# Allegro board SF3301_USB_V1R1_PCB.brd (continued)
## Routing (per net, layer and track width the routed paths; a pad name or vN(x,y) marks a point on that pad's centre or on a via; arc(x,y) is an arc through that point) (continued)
6314_ISEN: length 46.5
  TOP w0.254: v1(82.26,75.71) 82.77,76.22 R190.1
  TOP w0.508: v1(85.18,65.42) 85.18,65.17 84.93,64.91 84.12,64.91 83.78,65.24 83.78,68.57 85.82,70.6 85.82,78.91 78.98,85.74 75.28,85.74 v1(75.15,85.87)
  BOTTOM w0.254: R202.1 v1(75.15,85.87) ; Q21.5 80.84,73.73 80.48,74.08 80.48,76.34 79.52,77.31 78.02,77.31 77.18,78.15 C361.2 77.05,78.37 75.02,78.37 74.74,78.66 U13.24
  BOTTOM w0.508: L6.2 v1(85.18,65.42)
  vias: v1(79.72,75.71) v1(79.72,74.44) v1(79.72,73.17) v1(79.72,71.9) v1(80.99,75.71) v1(80.99,74.44) v1(80.99,73.17) v1(80.99,71.9) v1(82.26,74.44) v1(82.26,73.17) v1(82.26,71.9) v1(83.53,75.71) v1(83.53,74.44) v1(83.53,73.17) v1(83.53,71.9)
6314_ISEN-: length 5.6
  BOTTOM w0.254: C364.2 R204.2 73.42,86.96 R202.2 C362.1 73.42,84.36 72.97,83.91 U13.15
ADJ_TP: length 27.9
  TOP w0.508: R59.1 17.26,64.76 R60.1
  TOP w0.635: v1(13.81,51.96) 15.19,53.34 15.19,62.36 17.24,64.4 R59.1
  BOTTOM w0.381: 9.87,46.42 9.64,46.19 9.64,45.28 10.41,44.51 11.01,44.51 C276.2 11.39,44.51 11.93,44.51 R76.2
  BOTTOM w0.635: v1(13.81,51.96) 9.87,48.02 9.87,46.42
BTC_GNDS_0: length 34.9
  TOP w0.381: U5.A20 38.64,73.1 38,73.1
  TOP w0.508: 38,73.1 37.88,73.1 v2(37.43,73.55) 37.18,73.8 37.18,85.61 38.93,87.36 J6.1
  TOP w0.762: J6.5 J6.3 J6.1
  BOTTOM w0.381: v2(37.43,73.55) 37.88,73.1 38.07,73.1 C38.1
BTC_GNDS_1: length 73.2
  TOP w0.381: U5.P1 49.42,57.48 49.42,56.95 v2(49.41,56.94) 49.79,56.56 55.06,56.56 55.59,56.02
  TOP w0.762: v1(59.73,87.65) 59.73,89.22 58.89,90.06 58.89,98.57 58.13,99.33 56.99,99.33 55.08,101.23 51.37,101.23 J8.1 J8.3 J8.5 ; v1(60.21,75.73) 60.21,74.23 61.94,72.51 61.94,57.67 60.29,56.02 55.59,56.02
  BOTTOM w0.381: C39.1 49.88,56.47 v2(49.41,56.94)
  BOTTOM w0.635: v1(59.73,87.65) 60.11,87.26 60.11,76.9 60.2,76.82 60.2,75.8 60.18,75.77 v1(60.21,75.73)
BTC_PGD: length 105.2
  TOP w0.254: v1(59.43,76.49) 59.55,76.62 61.51,76.62 62.7,75.43 62.7,74.39 64.46,72.63 64.46,58.94 65.12,58.28 65.12,53.36 62.45,50.69 37.94,50.69 34,46.75 34,34.94 31.08,32.02 25.24,32.02 v1(23.97,30.75)
  BOTTOM w0.254: R127.2 22.85,29.37 23.97,30.5 v1(23.97,30.75) ; R152.2 61.43,91.96 60.8,91.96 R233.2 R181.2 60.16,89.58 58.99,88.41 58.99,83.2 59.32,82.87 59.32,76.6 v1(59.43,76.49)
BTC_VDD: length 322
  TOP w0.381: v2(46.64,56.3) U5.M1 v2(48.24,57.9) U5.N2 U5.P3 v2(49.84,59.5) U5.R4 ; U5.K13 v2(45.84,67.5) U5.J14 U5.H15 v2(44.24,69.1) U5.G16 U5.E18 v2(41.84,71.5) U5.D19 U5.C20 v2(40.24,73.1) ; v2(38.64,62.7) U5.A8 U5.B9 v2(40.24,64.3) U5.C10 U5.D11 v2(41.84,65.9) U5.E12 ; U5.P9 v2(49.04,63.5) U5.N8 U5.M7 v2(47.44,61.9) v2(46.64,61.1) U5.K5 U5.J4 v2(45.04,59.5) U5.H3 U5.G2 v2(43.44,57.9) U5.F1 v2(41.84,56.3) ; U5.U2 v2(51.44,57.9) U5.T1 ; U5.J20 v2(45.84,73.1) U5.K21 ; U5.J20 U5.K19 v2(46.64,72.3) U5.L20 ; U5.J20 v2(45.04,73.1) U5.H21 ; v2(40.24,56.3) U5.D1 v2(41.84,57.9) U5.E2 U5.F3 v2(43.44,59.5) U5.G4 U5.H5 v2(45.04,61.1) v2(45.84,61.9) U5.K7 U5.L8 v2(47.44,63.5) U5.M9 U5.N10 v2(49.04,65.1) U5.P11 ; U5.N12 v2(48.24,65.9) U5.M11 v2(47.44,65.1) U5.L10 U5.K9 v2(45.84,63.5) U5.J8 U5.H7 v2(44.24,61.9) v2(43.44,61.1) U5.F5 U5.E4 v2(41.84,59.5) U5.D3 U5.C2 v2(40.24,57.9) U5.B1 ; v2(38.64,57.9) U5.A2 U5.B3 v2(40.24,59.5) U5.C4 U5.D5 v2(41.84,61.1) U5.E6 U5.G8 v2(44.24,63.5) U5.H9 U5.J10 v2(45.84,65.1) U5.K11 v2(46.64,65.9) U5.L12 ; U5.U4 v2(51.44,59.5) U5.T3 U5.R2 v2(49.84,57.9) ; v2(38.64,71.5) U5.A18 U5.B17 v2(40.24,69.9) U5.C16 U5.D15 v2(41.84,68.3) U5.E14 ; U5.N22 v2(48.24,73.9) U5.M21 ; U5.D21 v2(41.84,73.1) U5.E20 U5.F19 v2(43.44,72.3) U5.G20 U5.H19 v2(45.04,71.5) v2(45.84,70.7) U5.K17 U5.L16 v2(47.44,69.1) U5.M15 U5.N14 v2(49.04,67.5) U5.P13 ; U5.D13 v2(41.04,67.5) U5.C14 v2(40.24,68.3) U5.B15 U5.A16 v2(38.64,69.9) ; U5.J12 v2(45.04,65.9) U5.H11 v2(44.24,65.1) U5.G10 U5.E8 v2(41.84,62.7) U5.D7 U5.C6 v2(40.24,61.1) U5.B5 U5.A4 v2(38.64,59.5) ; U5.P15 v2(49.04,69.1) U5.N16 U5.M17 v2(47.44,70.7) ; U5.N17 v2(49.04,70.7) U5.P17 ; v2(38.64,64.3) U5.A10 U5.B11 v2(40.24,65.9) U5.C12 ; U5.H13 v2(44.24,67.5) U5.G14 U5.E16 v2(41.84,69.9) U5.D17 U5.C18 v2(40.24,71.5) U5.B19 ; v2(38.64,65.9) U5.A12 U5.B13 v2(39.44,67.5) U5.A14 v2(38.64,68.3) ; v2(38.64,61.1) U5.A6 U5.B7 v2(40.24,62.7) U5.C8 U5.D9 v2(41.84,64.3) U5.E10 v2(43.44,65.9) U5.G12 ; v2(45.04,56.3) U5.K1 v2(46.64,57.9) U5.L2 U5.M3 v2(48.24,59.5) U5.N4 U5.P5 v2(49.84,61.1) ; v2(44.24,70.7) U5.H17 U5.J16 v2(45.84,69.1) U5.K15 U5.L14 v2(47.44,67.5) U5.M13 ; U5.P7 v2(49.04,61.9) v2(48.24,61.1) U5.M5 U5.L4 v2(46.64,59.5) U5.K3 U5.J2 v2(45.04,57.9) U5.H1 v2(43.44,56.3)
  TOP w0.508: v1(14.92,46.99) 18.12,50.19 18.12,52.06 ; v1(14.01,46.11) 13.93,46.19 13.93,48.4 16.22,50.69 16.22,52.09
  ART02 w0.508: v1(21.68,47.51) 21.68,46.12 24.57,43.23 32.64,43.23 36.35,39.52 37.69,39.52 v1(38.7,40.53) ; v1(27.14,44.47) 27.14,44.59 27.9,45.35 33.57,45.35 36.64,48.43 60.01,48.43 61.31,47.13 61.31,43.7 62.3,42.71 64.33,42.71 64.73,43.12 v1(64.73,43.96) ; v1(16.6,56.66) 16.6,56.02 23.6,49.03 v1(23.6,46.57) ; v1(25.98,46.5) 25.98,52.03 25.42,52.59 25.42,81.98 27.4,83.96 27.4,94.88 24.6,97.68 v1(24.6,98.06)
  BOTTOM w0.305: R95.1 v1(14.01,46.11) ; R92.1 v1(14.92,46.99)
  BOTTOM w0.381: D6.A 20.76,52.95 21.51,52.95 ; R89.1 16.8,47.96 17.31,47.96 21.51,52.17
  BOTTOM w0.508: 30.39,48.33 30.32,48.25 R70.1 ; v1(21.68,47.51) 21.68,47.44 C280.1 ; v1(23.6,46.57) 23.6,45.77 C282.1 ; C284.1 27.14,43.92 v1(27.14,44.47) ; v1(25.98,46.5) 25.98,44.55 C283.1
  vias: v1(16.6,59.2) v1(16.6,57.93) v1(17.62,59.2) v1(17.62,57.93) v1(17.62,56.66) v1(20.79,59.2) v1(20.79,57.93) v1(20.79,56.66) v1(22.06,59.2) v1(22.06,57.93) v1(22.06,56.66) v1(23.33,109.36) v1(23.33,108.09) v1(23.33,106.82) v1(23.33,105.55) v1(23.33,104.28) v1(23.33,103.01) v1(23.33,101.74) v1(23.33,100.47) v1(23.33,99.2) v1(23.33,65.42) v1(23.33,64.15) v1(23.33,62.88) v1(23.33,61.61) v1(23.33,60.34) v1(23.33,59.2) v1(23.33,57.93) v1(23.33,56.66) v1(23.33,54.75) v1(23.33,52.97) v1(24.6,109.36) v1(24.6,108.09) v1(24.6,106.82) v1(24.6,105.55) v1(24.6,104.28) v1(24.6,103.01) v1(24.6,101.74) v1(24.6,100.47) v1(24.6,99.2) v1(25.87,97.93) v1(26.51,67.07) v1(26.51,65.8) v1(26.51,64.53) v1(26.51,62.37) v1(26.51,60.47) v1(26.51,57.93) v1(26.51,56.02) v1(27.14,97.93) v1(27.14,76.98) v1(27.14,74.44) v1(27.14,68.09) v1(27.14,63.64) v1(27.78,96.66) v1(27.78,81.42) v1(27.78,80.15) v1(27.78,78.88) v1(28.41,109.36) v1(28.41,108.09) v1(28.41,100.47) v1(28.41,99.2) v1(28.41,97.93) v1(28.41,68.09) v1(28.41,63.64) v1(28.41,62.37) v1(28.41,60.47) v1(28.41,57.93) v1(28.41,56.02) v1(28.67,76.98) v1(28.67,74.44) v1(29.05,96.66) v1(29.05,94.12) v1(29.05,91.58) v1(29.05,89.68) v1(29.05,87.77) v1(29.05,83.96) v1(29.05,82.69) v1(29.05,81.42) v1(29.05,80.15) v1(29.05,78.88) v1(29.05,67.07) v1(29.05,65.8) v1(29.05,64.53) v1(29.68,109.36) v1(29.68,108.09) v1(29.68,100.47) v1(29.68,99.2) v1(29.68,97.93) v1(30.32,96.66) v1(30.32,94.12) v1(30.32,91.58) v1(30.32,89.68) v1(30.32,87.77) v1(30.32,83.96) v1(30.32,82.69) v1(30.32,81.42) v1(30.32,80.15) v1(30.32,76.98) v1(30.32,74.44) v1(30.32,67.07) v1(30.32,65.8) v1(30.32,64.53) v1(30.95,109.36) v1(30.95,108.09) v1(30.95,106.82) v1(30.95,105.55) v1(30.95,104.28) v1(30.95,103.01) v1(30.95,101.74) v1(30.95,100.47) v1(30.95,99.2) v1(30.95,97.93) v1(31.59,96.66) v1(31.59,94.12) v1(31.59,91.58) v1(31.59,89.68) v1(31.59,87.77) v1(31.59,83.96) v1(31.59,82.69) v1(31.59,81.42) v1(31.59,67.07) v1(31.59,65.8) v1(31.59,64.53) v1(31.59,63.26) v1(31.59,61.74) v1(31.59,60.47) v1(32.86,96.66) v1(32.86,94.12) v1(32.86,91.58) v1(32.86,89.68) v1(32.86,87.77) v1(32.86,85.23) v1(32.86,83.96) v1(32.86,80.91) v1(32.86,78.12) v1(32.86,76.98) v1(32.86,74.44) v1(32.86,67.07) v1(32.86,65.8) v1(32.86,64.53) v1(32.86,63.26) v1(32.86,61.74) v1(32.86,60.47) v1(33.49,70.12) v1(33.49,68.09) v1(34.13,94.12) v1(34.13,91.58) v1(34.13,89.68) v1(34.13,87.77) v1(34.13,85.23) v1(34.13,83.96) v1(34.13,80.91) v1(34.13,78.12) v1(34.13,76.98) v1(34.13,74.44) v1(34.13,71.9) v1(34.13,63.26) v1(34.13,61.74) v1(34.13,60.47) v1(34.76,69.99) v1(34.76,68.09) v1(35.27,59.2) v1(35.27,56.66) v1(35.27,55.39) v1(35.27,54.12) v1(35.4,94.12) v1(35.4,91.58) v1(35.4,89.68) v1(35.4,87.77) v1(35.4,85.23) v1(35.4,83.96) v1(35.4,80.91) v1(35.4,78.12) v1(35.4,76.98) v1(35.4,74.44) v1(35.4,73.17) v1(35.4,71.9) v1(36.03,69.99) v1(36.03,68.09) v1(36.03,67.07) v1(36.03,65.8) v1(36.03,64.53) v1(36.03,63.26) v1(36.03,61.74) v1(36.03,60.47) v1(36.41,75.71) v1(36.41,74.44) v1(36.41,73.17) v1(36.67,71.9) v1(36.67,59.2) v1(36.67,56.66) v1(37.43,55.39) v1(37.43,54.12) v1(37.94,45.23) v1(37.94,43.96) v1(38.57,46.24) v1(39.21,45.23) v1(39.21,43.96) v1(39.84,55.39) v1(39.84,54.12) v1(39.84,46.37) v1(40.48,45.23) v1(40.48,43.96) v1(41.11,46.5) v1(41.49,53.61) v1(42.38,46.5) v1(43.02,53.61) v1(43.65,46.5) v1(44.54,55.39) v1(44.54,54.12) v1(44.92,46.5) v1(46.19,46.5) v1(46.83,55.39) v1(46.83,54.12) v1(47.46,46.5) v1(47.46,45.23) v1(47.46,43.96) v1(48.1,55.39) v1(48.73,46.5) v1(48.73,45.23) v1(48.73,43.96) v1(48.99,54.12) v1(50,46.5) v1(50,45.23) v1(50,43.96) v1(50.64,54.12) v1(50.76,55.77) v1(51.27,46.5) v1(51.27,45.23) v1(51.78,53.74) v1(51.91,55.77) v1(52.54,46.5) v1(52.54,45.23) v1(52.54,43.96) v1(53.3,55.77) v1(53.43,53.74) v1(53.81,46.5) v1(53.81,45.23) v1(54.57,54.24) v1(54.57,43.96) v1(54.7,55.77) v1(55.08,46.5) v1(55.08,45.23) v1(56.35,46.5) v1(56.35,45.23) v1(56.61,43.96) v1(57.62,46.5) v1(57.62,45.23) v1(58.64,43.96) v1(58.89,45.23) v1(62.45,46.37) v1(62.45,45.23) v1(62.45,43.96) v1(63.59,46.37) v1(63.59,45.23) v1(63.59,43.96) v1(64.61,48.78) v1(64.61,47.64) v1(64.61,46.37) v1(64.73,45.23) v1(66.13,46.37) v1(67.91,48.78) v1(67.91,47.64) v1(67.91,46.37) v1(68.93,47.64) v1(68.93,46.5) v1(69.94,47.64) v1(69.94,46.37) v1(70.83,46.5) v1(70.83,45.1) v1(70.83,43.83) v1(71.97,46.5) v1(72.1,45.1) v1(72.1,43.83) v1(73.37,45.1) v1(73.37,43.83)
BTC_VDDS_0: length 43.2
  TOP w0.381: v2(38.52,73.9) 38.64,73.9 U5.A21
  TOP w0.508: v2(38.52,73.9) 38.35,73.9 37.94,74.31 37.94,84.98 39.84,86.88 39.84,96.79 40.6,97.55 40.6,106.8 38.93,108.47
  TOP w0.762: 38.93,108.47 33.85,108.47
  BOTTOM w0.381: v2(38.52,73.9) 38.17,74.25 C38.2
BTC_VDDS_1: length 80.5
  TOP w0.381: U5.P2 v2(49.04,57.9) ; 55.97,55.01 49.75,55.01 v2(49.11,55.64)
  TOP w0.762: v1(60.75,87.95) 60.75,89.7 59.91,90.54 59.91,99.3 50.74,108.47 44.64,108.47 ; v1(61.2,75.76) 61.2,74.67 62.96,72.91 62.96,57.17 60.8,55.01 55.97,55.01
  BOTTOM w0.381: v2(49.11,55.64) 48.86,55.9 C39.2 48.83,56.3 48.83,57.69 v2(49.04,57.9)
  BOTTOM w0.635: v1(61.2,75.76) 61.2,77.03 60.98,77.26 60.98,87.72 v1(60.75,87.95)
DNRX0: length 48.1
  TOP w0.254: v1(71.72,53.74) 72.86,54.88 72.86,56.53 67.83,61.56 67.83,73.67 62.62,78.88 51.53,78.88 v1(51.02,78.37)
  TOP w0.381: U5.R22 v2(50.64,74.7)
  BOTTOM w0.254: v1(51.02,78.37) 51.12,78.27 51.12,76.95 50.46,76.29 50.46,74.89 v2(50.64,74.7) ; 70.83,53.61 70.96,53.74 v1(71.72,53.74) 72.38,53.74 R33.1
DNRX1: length 40.2
  TOP w0.254: v1(71.72,55.64) 66.82,60.54 66.82,73.24 62.19,77.87 54.32,77.87 53.56,77.1 52.42,77.1 52.03,76.72 52.03,75.29 U5.U23
  BOTTOM w0.254: 70.83,55.64 v1(71.72,55.64) 72.51,55.64 R41.1
DNTX0: length 44.3
  TOP w0.254: v1(71.72,54.63) 72.35,55.26 72.35,56 67.33,61.03 67.33,73.5 62.45,78.37 52.03,78.37 51.4,77.74 51.4,76.47 50.24,75.31 U5.R23
  BOTTOM w0.254: 70.83,54.63 v1(71.72,54.63) 72.51,54.63 R35.1
DNTX1: length 47.3
  TOP w0.254: v1(51.02,79.39) 63.85,79.39 65.37,77.87 65.37,76.88 68.34,73.9 68.34,62.07 v1(72.99,57.42)
  TOP w0.381: U5.U22 v2(51.44,74.7)
  BOTTOM w0.254: v1(72.99,57.42) 72.53,56.96 R37.1 72.51,56.66 70.83,56.66 ; v1(51.02,79.39) 51.63,78.78 51.63,76.7 50.97,76.04 50.97,75.18 v2(51.44,74.7)
FB_VSS: length 32.1
  BOTTOM w0.203: 16.1,35.44 U11.3
  BOTTOM w0.254: 16.1,35.44 15.97,35.31 15.97,34.69
  BOTTOM w0.381: 19.51,30.1 18.24,31.37 18.14,31.37 15.97,33.54 15.97,34.69
  BOTTOM w0.508: R122.2 29.3,42.97 C271.1
  BOTTOM w0.635: 19.51,30.1 21.29,28.31 26.02,28.31 29.48,31.77 29.48,42.13 29.33,42.28 C271.1
ISL6314_VID0: length 3.1
  BOTTOM w0.254: R199.2 70.47,77.25 U13.31
ISL6314_VID1: length 2.8
  BOTTOM w0.254: R198.2 69.94,75.96 70.97,76.99 U13.30
ISL6314_VID2: length 2.5
  BOTTOM w0.254: R197.2 71.08,76.22 71.47,76.6 U13.29
ISL6314_VID3: length 2.5
  BOTTOM w0.254: R196.2 72.23,76.6 71.97,76.85 U13.28
ISL6314_VID4: length 2.7
  BOTTOM w0.254: R195.2 73.37,76.22 72.47,77.12 U13.27
ISL6314_VID5: length 3
  BOTTOM w0.254: R194.2 74.51,75.83 72.97,77.38 U13.26
ISL6314_VID6: length 3.3
  BOTTOM w0.254: U13.25 73.47,77.77 R193.2
ISL6314_VID7: length 3.6
  BOTTOM w0.254: R191.2 68.42,76.34 68.8,76.34 69.97,77.51 U13.32
ISN1: length 6.9
  BOTTOM w0.229: U11.18 15.89,42.81 15.89,43.71
  BOTTOM w0.254: R85.2 13.35,46.79 13.35,45.88 14.57,44.66 14.91,44.66 R95.2 15.89,44.23 15.89,43.71
ISN24: length 7.2
  BOTTOM w0.229: U11.19 16.59,42.83 16.59,44.41
  BOTTOM w0.254: R87.2 14.29,46.72 15.47,45.54 15.83,45.54 16.09,45.8 R92.2 16.59,45.31 16.59,44.41
ISN35: length 7.5
  BOTTOM w0.229: U11.20 17.25,42.89 17.25,44.92
  BOTTOM w0.254: R79.2 15.18,47.7 16.4,46.48 16.75,46.48 R89.2 17.25,46.52 17.25,44.92
ISP1: length 7
  BOTTOM w0.203: 22.21,42.36 20.77,42.36 20.35,41.93 20.35,41.86 19.82,41.34 U11.25
  BOTTOM w0.381: 22.21,42.36 23.4,41.17 24.39,41.17 C284.2
  BOTTOM w0.508: R96.2 24.55,41.33 C284.2
ISP2: length 5.2
  BOTTOM w0.203: 22.05,42.94 20.7,42.94 19.89,42.12 19.89,42.11 U11.24
  BOTTOM w0.254: 22.05,42.94 22.24,43.13 R93.2
  BOTTOM w0.381: C283.2 R93.2
ISP3: length 4.8
  BOTTOM w0.203: 19.91,42.85 19.61,42.55 U11.23
  BOTTOM w0.254: 20.67,43.6 19.91,42.85
  BOTTOM w0.381: R90.2 C282.2 21.44,43.6 20.67,43.6
ISP4: length 5.2
  BOTTOM w0.203: U11.22 19.78,43.43 19.78,43.65
  BOTTOM w0.381: C280.2 19.78,45.54 19.78,43.65
  BOTTOM w0.508: R86.2 C280.2
ISP5: length 5.7
  BOTTOM w0.203: U11.21 18.89,43.26 18.89,43.66
  BOTTOM w0.381: 18.89,43.66 18.89,45.55 18.13,46.31 18.13,47.48 R103.2
LTC_PGD: length 79.8
  TOP w0.254: v1(25.62,31.38) 31.21,31.38 34.51,34.69 34.51,46.5 38.19,50.18 62.96,50.18 65.62,52.85 65.62,58.54 65.12,59.05 v1(65.12,72.02)
  BOTTOM w0.254: v1(25.62,31.38) 24.86,32.15 R110.2 ; R173.1 65.8,73.85 65.8,72.71 v1(65.12,72.02)
LTC_PGD_R: length 6.2
  BOTTOM w0.203: C359.1 67.76,76.9 68.6,76.9 69.27,77.58 U13.1 ; C359.1 67.58,76.77 67.15,77.21 67.11,77.21 66.55,77.76 R143.2 ; C359.1 67.58,76.65 R173.2
LTC_VDD: length 116.6
  TOP w0.381: U5.AB1 v2(56.24,57.9) U5.AC2 v2(57.04,57.9) ; U5.T7 v2(50.64,62.7) U5.R8 ; v2(57.04,61.1) U5.AC6 v2(56.24,61.1) U5.AB5 U5.AA4 v2(54.64,59.5) U5.Y3 U5.W2 v2(53.04,57.9) U5.V1 ; U5.T19 v2(51.44,71.5) ; U5.W16 v2(53.84,69.9) U5.Y17 U5.AA18 v2(55.44,71.5) U5.AB19 U5.AC20 v2(57.04,73.1) ; v2(53.04,62.7) U5.W8 U5.Y9 v2(54.64,64.3) U5.AA10 U5.AB11 v2(56.24,65.9) U5.AC12 v2(57.04,65.9) ; v2(57.04,59.5) U5.AC4 v2(56.24,59.5) U5.AB3 U5.AA2 v2(54.64,57.9) U5.Y1 ; v2(57.04,64.3) U5.AC10 v2(56.24,64.3) U5.AB9 U5.AA8 v2(54.64,62.7) U5.Y7 U5.W6 v2(53.04,61.1) U5.V5 ; U5.R12 v2(50.64,65.9) U5.T11 U5.U10 v2(52.24,64.3) ; U5.V3 v2(53.04,59.5) U5.W4 U5.Y5 v2(54.64,61.1) U5.AA6 U5.AB7 v2(56.24,62.7) U5.AC8 v2(57.04,62.7) ; v2(52.24,68.3) U5.U14 U5.T15 51.04,68.7 v2(50.64,69.1) U5.R16 ; U5.Y21 v2(53.84,73.1) U5.W20 v2(53.04,73.1) U5.V21 ; v2(52.24,65.9) U5.U12 U5.T13 51.04,67.1 v2(50.64,67.5) U5.R14 ; v2(52.24,69.9) U5.U16 U5.T17 v2(50.64,70.7) ; U5.AB21 v2(55.44,73.1) U5.AA20 U5.Y19 v2(53.84,71.5) U5.W18 v2(53.04,71.5) U5.V19 U5.U20 v2(51.44,73.1) U5.T21 ; v2(51.44,61.1) U5.T5 ; U5.W14 v2(53.84,68.3) U5.Y15 U5.AA16 v2(55.44,69.9) U5.AB17 U5.AC18 v2(57.04,71.5) ; v2(57.04,68.3) U5.AC14 v2(56.24,67.5) U5.AB13 U5.AA12 v2(54.64,65.9) U5.Y11 U5.W10 v2(53.04,64.3) ; U5.R10 v2(50.64,64.3) U5.T9 U5.U8 v2(52.24,62.7) ; v2(53.04,65.9) U5.W12 U5.Y13 v2(54.64,67.5) U5.AA14 v2(55.44,68.3) U5.AB15 U5.AC16 v2(57.04,69.9) ; v2(53.04,73.9) U5.W22
  TOP w0.508: v1(85.18,64.02) 85.03,64.18 83.81,64.18 83.05,64.94 83.05,68.88 83.48,69.31 85.08,70.91 85.08,78.6 78.68,85 75.3,85 v1(75.15,84.85)
  BOTTOM w0.254: v1(75.15,84.85) C362.2 74.44,84.65 73.47,83.68 U13.16
  BOTTOM w0.305: R206.1 R208.2 ; R208.2 61.31,71.26 ; R208.2 60.62,72.15 60.59,72.13
  BOTTOM w0.508: L6.1 v1(85.18,64.02)
  vias: v1(58.26,69.99) v1(58.26,68.09) v1(58.38,72.66) v1(58.89,66.18) v1(58.89,64.28) v1(58.89,63.01) v1(58.89,61.74) v1(58.89,60.47) v1(58.89,59.2) v1(58.89,57.93) v1(59.53,72.66) v1(59.53,69.99) v1(59.53,68.09) v1(60.16,66.18) v1(60.16,64.28) v1(60.16,63.01) v1(60.16,61.74) v1(60.16,60.47) v1(60.16,59.2) v1(60.16,57.93) v1(60.54,72.66) v1(60.8,69.99) v1(60.8,68.09) v1(70.36,60.88) v1(71.97,59.32) v1(77.82,57.55) v1(79.72,59.96) v1(79.72,57.55) v1(79.85,64.28) v1(79.85,62.88) v1(79.85,61.48) v1(81.5,61.36) v1(81.5,59.96) v1(82.26,57.67) v1(84.42,57.67) v1(86.07,57.67) v1(88.23,61.61) v1(88.23,60.34) v1(88.23,59.07)
OSC_BP: length 11.6
  TOP w0.254: U5.P23 49.75,75.41 49.75,77.74 50.26,78.25 50.26,79.52 50.89,80.15 v1(54.12,80.15)
  BOTTOM w0.305: v1(54.12,80.15) 54.12,80.71 54.65,81.24 R44.1 54.93,82.34 R39.1
OSC_EN: length 16.7
  TOP w0.254: v1(53.18,97.42) 53.18,96.92 54.06,96.03 X1.1
  BOTTOM w0.254: Q24.3 56.99,96.92 57.62,96.28 C354.2 ; 54.19,91.2 54.19,91.96 54.07,92.09 54.07,95.01 53.56,95.52 R186.2 v1(53.18,97.42)
  BOTTOM w0.305: v1(53.18,97.42) 54.07,98.31 Q24.3
OSC_ZO: length 17.9
  TOP w0.254: U5.E23 42.26,75.12 42.26,85.35 44.67,87.77 45.56,88.65 R38.2
PSU_12V:
  vias: v1(49.37,16.65) v1(49.37,15.38) v1(49.37,14.11) v1(49.37,12.84) v1(50.64,16.65) v1(50.64,15.38) v1(50.64,14.11) v1(50.64,12.84) v1(55.97,16.65) v1(55.97,15.38) v1(55.97,14.11) v1(56.86,16.65) v1(56.86,15.38) v1(56.86,14.11)
PWM1: length 54.9
  ART02 w0.508: v1(55.46,35.96) 55.59,35.83 55.59,30.11 53.18,27.7 40.6,27.7 39.72,28.59 39.72,29.23 37.18,31.77 37.18,34.68 31.71,40.15 25.87,40.15 25.17,40.85 24.04,40.85 23.02,39.84 21.81,39.84 20.93,40.71 v1(20.93,41.69)
  BOTTOM w0.203: v1(20.93,41.69) 20.91,41.69 U11.26
  BOTTOM w0.508: 53.05,37.42 54,37.42 v1(55.46,35.96)
PWM2: length 57.1
  TOP w0.508: U9.2 v1(15.46,79.39)
  ART02 w0.508: v1(15.46,79.39) 14.54,78.48 10.51,78.48 7.08,75.05 7.08,53.86 7.71,53.23 7.71,49.67 12.66,44.72 19.27,44.72 21.94,42.05 v1(21.94,41.38)
  BOTTOM w0.203: U11.27 21.04,41.11 21.22,41.11 21.28,41.16 21.72,41.16 v1(21.94,41.38)
PWM3: length 56.5
  ART02 w0.508: v1(16.79,79.39) 16.79,78.79 15.2,77.21 10.73,77.21 8.47,74.95 8.47,55.64 12.03,52.09 12.03,50.82 14.82,48.02 17.11,48.02 22.7,42.43 22.7,40.98 v1(22.57,40.85)
  BOTTOM w0.203: U11.28 21.31,40.66 21.38,40.66 21.4,40.67 22.38,40.67 22.39,40.67 v1(22.57,40.85)
  BOTTOM w0.508: U10.2 v1(16.79,79.39)
PWM4: length 49.3
  ART02 w0.508: v1(55.72,26.3) 53.69,24.27 40.73,24.27 35.65,29.35 35.65,34.05 32.45,37.25 30.04,37.25 28.92,38.37 25.94,38.37 v1(24.48,39.84)
  BOTTOM w0.203: 22.57,39.84 22.19,40.22 21.59,40.22 U11.29
  BOTTOM w0.254: v1(24.48,39.84) 22.57,39.84
  BOTTOM w0.508: U12.2 57.82,29.17 55.72,27.07 v1(55.72,26.3)
PWM5: length 5.2
  BOTTOM w0.254: R83.2 26.15,39.15 22,39.15 U11.30
RST_SF3301: length 202.2
  TOP w0.254: R220.2 70.58,7.13 70.7,7 v1(70.83,7) ; U5.M23 47.72,75.23 47.72,76.93 v1(48.4,77.61) 49.75,78.96 49.75,80.28 51.02,81.55 62.5,81.55 65.88,78.17 65.88,77.1 68.98,74.01 68.98,63.34 73.75,58.56 73.75,54.63 72.23,53.1 67.4,53.1 63.46,49.16 39.44,49.16 35.65,45.38 35.65,34.05 v1(33.24,31.64) ; v1(46.7,82.82) 49.24,85.36 v1(49.24,88.28)
  BOTTOM w0.203: Q26.3 48.35,89.17 C356.2 49.08,88.41 49.24,88.25 ; 49.24,88.25 v1(49.24,88.28) ; 49.24,88.25 49.51,87.98 D19.A ; R28.2 v1(46.7,82.82)
  BOTTOM w0.254: v1(48.4,77.61) 48.46,77.67 48.46,80.81 47.46,81.8 R28.2 ; v1(33.24,31.64) 27.52,25.92 25.75,25.92 25.11,25.29 25.11,20.34 26.89,18.56 29.17,18.56 30,17.73 SW1.2 30.01,5.73 55.59,5.73 56.99,4.33 65.98,4.33 68.65,7 v1(70.83,7)
RT8802A_PHASE1: length 56.4
  ART02 w0.508: v1(28.16,44.47) 33.8,44.47 37,47.67 59.5,47.67 60.54,46.62 60.54,43.37 62.12,41.8 65.5,41.8 66.77,40.53 66.77,36.46 v1(66.51,36.21)
  BOTTOM w0.508: v1(60.92,36.34) 59.84,37.42 U8.7 ; v1(28.16,44.47) 28.16,43.14 R96.1 ; C251.1 v1(59.34,34.25)
  vias: v1(60.92,35.45) v1(60.92,34.18) v1(60.92,32.91) v1(62.45,36.34) v1(62.45,35.45) v1(62.45,34.18) v1(62.45,32.91) v1(62.7,31.64) v1(62.83,30.62) v1(62.83,29.73) v1(63.85,36.34) v1(63.85,35.45) v1(63.85,34.18) v1(63.85,32.91) v1(64.1,31.64) v1(64.1,30.62) v1(64.1,29.73) v1(65.12,36.34) v1(65.12,35.45) v1(65.12,34.18) v1(65.12,32.91) v1(65.75,31.13) v1(66.51,35.32) v1(66.51,34.05) v1(66.51,32.78) v1(67.02,31.13) v1(68.16,36.21) v1(68.16,35.32) v1(68.16,34.05) v1(68.16,32.78) v1(68.54,31.51) v1(68.54,30.62) v1(68.54,29.48) v1(69.56,36.21) v1(69.56,35.32) v1(69.56,34.05) v1(69.56,32.78) v1(69.81,31.51) v1(69.81,30.5) v1(69.81,29.48) v1(71.08,31.51) v1(71.08,30.37) v1(71.08,29.48) v1(71.34,32.78)
RT8802A_PHASE2: length 65
  TOP w0.508: C259.1 12.16,85.61 11.39,86.38 11.39,88.08 ; U9.7 15.46,88.03 v1(15.71,88.28)
  ART02 w0.508: v1(25.13,46.5) 25.13,51.7 24.65,52.19 24.65,82.41 26.63,84.39 26.63,94.51 21.43,99.71 v1(21.43,100.47)
  BOTTOM w0.508: R93.1 25.13,45.5 v1(25.13,46.5)
  vias: v1(10.38,97.17) v1(10.38,95.85) v1(10.38,94.58) v1(10.89,91.46) v1(10.89,90.06) v1(10.89,88.79) v1(11.27,98.57) v1(11.52,97.17) v1(11.52,95.85) v1(11.52,94.58) v1(11.78,91.46) v1(11.78,90.06) v1(11.78,88.79) v1(12.54,98.57) v1(13.05,95.52) v1(13.05,94.12) v1(13.05,92.73) v1(13.05,89.93) v1(13.05,88.28) v1(13.3,97.17) v1(13.3,91.46) v1(13.81,99.84) v1(13.81,98.57) v1(14.57,97.17) v1(14.57,95.52) v1(14.57,94.12) v1(14.57,92.73) v1(14.57,91.46) v1(14.7,89.93) v1(14.7,88.28) v1(15.08,109.36) v1(15.08,108.09) v1(15.08,106.82) v1(15.08,105.55) v1(15.08,104.28) v1(15.08,103.01) v1(15.08,101.11) v1(15.08,99.84) v1(15.08,98.57) v1(15.59,97.17) v1(15.59,95.52) v1(15.59,94.12) v1(15.59,92.73) v1(15.59,91.46) v1(15.71,89.93) v1(16.35,109.36) v1(16.35,108.09) v1(16.35,101.11) v1(16.35,99.84) v1(16.35,98.57) v1(16.73,97.17) v1(16.73,95.52) v1(16.73,94.12) v1(16.73,92.73) v1(16.73,91.46) v1(16.86,89.93) v1(16.86,88.28) v1(17.62,109.36) v1(17.62,108.09) v1(17.62,101.11) v1(17.62,99.84) v1(17.62,98.57) v1(17.62,97.17) v1(17.62,95.52) v1(17.62,94.12) v1(17.62,92.73) v1(17.62,91.46) v1(17.74,89.93) v1(17.74,88.28) v1(18.89,98.57) v1(21.43,109.36) v1(21.43,108.09) v1(21.43,106.82) v1(21.43,105.55) v1(21.43,104.28) v1(21.43,103.01) v1(21.43,101.74)
RT8802A_PHASE3: length 20.4
  TOP w0.508: C277.1 10.76,77.38
  ART02 w0.508: v1(13.93,56.66) 14.82,56.66 22.82,48.66 22.82,46.66 v1(22.7,46.54)
  BOTTOM w0.508: 16.79,76.47 16.79,75.39 v1(17.24,74.95) ; R90.1 22.57,46.54 v1(22.7,46.54)
  vias: v1(9.62,68.6) v1(9.62,67.2) v1(9.62,65.93) v1(9.62,65.17) v1(9.62,59.2) v1(9.62,57.93) v1(9.62,56.66) v1(10,74.26) v1(10,72.99) v1(10.89,74.95) v1(10.89,73.68) v1(10.89,72.41) v1(10.89,71.39) v1(10.89,68.85) v1(10.89,67.58) v1(10.89,65.93) v1(10.89,65.17) v1(10.89,59.2) v1(10.89,57.93) v1(10.89,56.66) v1(12.16,74.95) v1(12.16,73.68) v1(12.16,72.41) v1(12.16,71.39) v1(12.16,69.99) v1(12.16,68.85) v1(13.43,74.95) v1(13.43,73.68) v1(13.43,72.41) v1(13.43,71.39) v1(13.43,69.99) v1(13.43,68.85) v1(13.93,65.29) v1(13.93,64.28) v1(13.93,63.01) v1(13.93,61.74) v1(13.93,60.47) v1(13.93,59.2) v1(13.93,57.93) v1(14.7,74.95) v1(14.7,73.68) v1(14.7,72.41) v1(14.7,71.39) v1(14.7,68.85) v1(14.7,67.58) v1(14.7,66.31) v1(15.97,74.95) v1(15.97,73.68) v1(15.97,72.41) v1(15.97,68.85) v1(15.97,67.58) v1(15.97,66.31) v1(16.98,67.58) v1(16.98,66.31) v1(17.24,73.68) v1(17.24,72.41) v1(17.24,68.85)
RT8802A_PHASE4: length 30.3
  ART02 w0.508: v1(40.6,36.08) 37.94,38.75 36.03,38.75 32.32,42.46 24.25,42.46 20.92,45.79 20.92,48.15 v1(21.05,48.28)
  BOTTOM w0.508: R86.1 20.72,48.28 v1(21.05,48.28) ; C286.1 52.87,32.34 v1(52.03,31.51) ; 53.05,29.17 51.72,29.17 v1(51.53,28.97)
  vias: v1(40.6,34.81) v1(40.6,33.54) v1(40.6,32.27) v1(40.86,31) v1(41.87,36.08) v1(41.87,34.81) v1(41.87,33.54) v1(41.87,32.27) v1(41.87,31) v1(43.14,36.08) v1(43.14,34.81) v1(43.14,33.54) v1(43.14,32.27) v1(43.14,30.88) v1(43.14,29.86) v1(44.41,36.08) v1(44.41,34.81) v1(44.41,33.54) v1(44.41,32.27) v1(44.41,30.88) v1(44.41,29.86) v1(45.94,36.08) v1(45.94,34.81) v1(45.94,33.54) v1(45.94,32.27) v1(46.32,31) v1(47.59,36.08) v1(47.59,34.81) v1(47.59,33.54) v1(47.59,32.27) v1(47.59,31) v1(48.86,36.08) v1(48.86,34.81) v1(48.86,33.54) v1(48.86,32.27) v1(48.86,30.88) v1(48.86,29.73) v1(50.13,36.08) v1(50.13,34.81) v1(50.13,33.54) v1(50.13,32.27) v1(50.13,30.88) v1(50.13,29.86)
RUN_LED: length 11.9
  TOP w0.254: U19.22 v1(67.15,20.21)
  BOTTOM w0.254: v1(67.15,20.21) 67.15,20.2 69.31,18.05 75.64,18.05 D1.C1
UART1_RX: length 3
  BOTTOM w0.254: U6.3 75.05,51.73 73.85,50.54 R49.2
UART1_RX_3V3: length 38
  TOP w0.254: v1(84.04,42.31) 84.04,35.07 81.96,32.98 81.96,24.48 75.97,18.49 74.58,18.49 71.44,15.36 68.85,15.36 U19.12
  BOTTOM w0.254: R9.2 83.66,42.69 v1(84.04,42.31)
UART1_TX: length 2.9
  BOTTOM w0.254: U6.1 75.02,50.43 74.11,49.52 R48.2
UART1_TX_3V3: length 37.1
  TOP w0.254: v1(84.67,43.45) 84.17,43.45 83.4,42.69 83.4,35.23 81.42,33.24 81.42,24.67 75.78,19.03 74.35,19.03 71.18,15.86 U19.13
  BOTTOM w0.254: R8.2 84.93,43.7 v1(84.67,43.45)
UART2_RX: length 2.7
  BOTTOM w0.254: R51.2 74.26,52.57 74.72,53.03 U6.5
UART2_RX_3V3: length 35.9
  TOP w0.254: U19.20 68.15,19.66 68.44,19.95 75.99,19.95 80.86,24.82 80.86,33.92 82.13,35.19 82.13,42.31 v1(82.26,42.43)
  BOTTOM w0.254: R11.2 81.12,43.58 v1(82.26,42.43)
UART2_TX: length 2.9
  BOTTOM w0.254: R50.2 73.98,51.55 74.81,52.38 U6.4
UART2_TX_3V3: length 35.7
  TOP w0.254: U19.21 67.65,19.85 68.27,20.46 75.78,20.46 80.36,25.03 80.36,34.31 81.63,35.58 81.63,42.81 v1(82.26,43.45)
  BOTTOM w0.254: v1(82.26,43.45) 82.39,43.58 R10.2
UPRX0: length 72.4
  TOP w0.254: v1(45.94,78.55) 45.81,78.68 45.81,80.28 46.19,80.66 47.03,80.66 50,83.63 63.46,83.63 65.48,81.61 68.48,81.61 68.8,81.3 68.8,78.91 68.04,78.15 68.04,77.74 68.72,77.05 69.89,77.05 73.57,73.37 73.57,62.65 76.42,59.81 76.42,53.48 72.48,49.55 v1(71.72,49.55)
  TOP w0.381: U5.J22 v2(45.84,74.7)
  BOTTOM w0.254: R48.1 72.51,49.55 v1(71.72,49.55) 70.83,49.55 ; v2(45.84,74.7) 46.57,75.43 46.57,77.92 v1(45.94,78.55)
UPRX1: length 62.1
  TOP w0.254: v1(71.72,51.32) 72.23,51.32 75.28,54.37 75.28,58.94 70.91,63.31 70.91,73.44 66.84,77.5 66.84,78.63 62.93,82.54 62.91,82.54 62.88,82.57 50.51,82.57 47.46,79.52 46.83,79.52 46.57,79.26 46.57,78.65 47.04,78.18 U5.L23
  BOTTOM w0.254: 70.83,51.58 71.47,51.58 v1(71.72,51.32) 71.95,51.55 R50.1
UPTX0: length 66.5
  TOP w0.254: v1(71.72,50.56) 72.48,50.56 75.91,53.99 75.91,59.3 72.23,62.98 72.23,73.93 69.87,76.29 68.8,76.29 67.33,77.77 67.33,78.96 66.05,80.23 65.62,80.66 63.19,83.1 50.26,83.1 47.18,80.03 v1(46.45,80.03)
  TOP w0.381: U5.J23 v2(45.84,75.5)
  BOTTOM w0.254: v1(46.45,80.03) 46.32,80.03 45.18,78.88 45.18,77.61 46.07,76.72 46.07,75.73 v2(45.84,75.5) ; R49.1 72.51,50.56 v1(71.72,50.56) 70.83,50.56
UPTX1: length 60
  TOP w0.254: v1(47.21,78.88) 47.59,78.88 50.76,82.06 62.73,82.06 66.36,78.43 66.36,77.3 69.74,73.93 69.74,63.59 74.62,58.71 74.62,54.47 72.48,52.34 v1(71.72,52.34)
  TOP w0.381: U5.L22 v2(47.44,74.7)
  BOTTOM w0.254: v2(47.44,74.7) 47.08,75.07 47.08,78.76 v1(47.21,78.88) ; 70.83,52.59 71.08,52.34 v1(71.72,52.34) 71.95,52.57 R51.1
USB_DM: length 6.8
  TOP w0.231: R23.1 60.09,17.59 v1(60.29,17.8) ; v1(64.13,16.7) 64.28,16.86 U19.4
  BOTTOM w0.231: v1(64.13,16.7) 64.02,16.7 64.02,16.71 64.01,16.7 61,16.7 60.29,17.41 v1(60.29,17.8)
USB_DP: length 5.9
  TOP w0.231: R24.1 61.36,17.62 v1(61.18,17.8) ; U19.3 64.33,17.36 v1(64.15,17.54)
  BOTTOM w0.231: v1(64.15,17.54) 64.02,17.54 63.77,17.29 61.25,17.29 61.05,17.48 61.05,17.67 v1(61.18,17.8)
VCORE: length 5.6
  BOTTOM w0.381: D6.C 16.67,49.04 15.73,49.98 R82.2 15.14,50.02 R79.1 R87.1 R85.1
VID0: length 42.6
  TOP w0.203: R129.2 25.29,32.65 v1(25.21,32.73) 25.19,32.73 24.86,32.4 18.91,32.4 12.55,38.76 12.55,41.15 12.55,41.18 10.94,42.79 10.94,42.79 10.61,43.12 10.61,43.12 10.12,43.6 10.12,44.59 9.11,45.61 9.11,51.4 9.06,51.45 v1(8.98,51.45)
  BOTTOM w0.203: U11.39 20.65,33.75 21.29,33.75 21.29,33.75 22.32,32.73 v1(25.21,32.73) 25.29,32.65 ; v1(8.98,51.45) 8.35,52.09 7.46,52.09 6.7,52.85 R128.1
  BOTTOM w0.254: 25.29,32.65 R129.2
VID1: length 42.9
  TOP w0.203: R131.2 25.64,33.31 24.97,33.31 24.69,33.04 22.34,33.04 v1(21.05,34.33) 17.62,34.33 13.05,38.9 13.05,42.36 9.62,45.79 9.62,51.63 8.98,52.26 v1(8.98,52.47)
  BOTTOM w0.203: R130.1 6.19,54.12 7.58,52.72 8.73,52.72 v1(8.98,52.47) ; U11.38 19.1,35.99 20.77,34.33 v1(21.05,34.33) 21.26,34.33 21.29,34.36 21.33,34.33 21.38,34.33 22.55,33.16 24.81,33.16 25.31,33.67 R131.2
VID2: length 43.2
  TOP w0.203: R133.2 25.75,34.69 24.81,33.75 v1(23.46,33.75) 22.49,33.75 21.3,34.94 17.67,34.94 13.55,39.06 13.55,42.48 10.07,45.96 10.07,51.83 9.62,52.29 9.62,52.72 v1(8.98,53.36)
  BOTTOM w0.203: U11.37 20.92,34.92 21.45,34.92 22.6,33.77 23.43,33.77 v1(23.46,33.75) 23.49,33.77 24.78,33.77 25.7,34.69 R133.2 ; v1(8.98,53.36) 7.84,53.36 5.93,55.26 R132.1
VID3: length 44.3
  TOP w0.203: v1(10.28,52.47) 10.56,52.19 10.56,46.12 14.06,42.61 14.06,39.18 17.87,35.37 21.5,35.37 21.99,34.89 v1(22.32,34.89) 22.32,34.69 22.7,34.31 24.6,34.31 R135.2
  BOTTOM w0.203: U11.36 21.2,35.35 21.78,35.35 22.32,34.81 ; v1(10.28,52.47) 10,52.75 10,53.18 9.19,53.99 7.84,53.99 6.7,55.13 6.7,56.02 6.06,56.66 R134.1 ; 22.32,34.81 22.8,34.33 24.7,34.33 24.98,34.61 24.98,34.81 25.87,35.7 R135.2 ; 22.32,34.81 v1(22.32,34.89)
VID4: length 38.3
  TOP w0.203: R137.2 23.08,34.94 22.44,35.58 21.94,35.58 v1(21.55,35.96) 17.92,35.96 14.57,39.31 14.57,42.74 11.78,45.53 11.78,51.12 11.39,51.5 v1(11.39,54.45)
  BOTTOM w0.203: U11.35 21.31,35.96 v1(21.55,35.96) 21.81,35.96 22.29,35.47 22.56,35.47 23.09,34.94 R137.2 ; R136.1 7.2,56.66 7.2,55.64 8.27,54.57 11.27,54.57 v1(11.39,54.45)
VID5: length 37.4
  TOP w0.203: R139.2 22.7,35.96 v1(22.44,36.21) 22.11,36.54 21.73,36.54 20.79,37.48 20.79,39.13 18,41.93 16.02,41.93 12.21,45.74 12.21,54.45 v1(12.28,54.37)
  BOTTOM w0.203: R139.2 22.95,36.21 v1(22.44,36.21) 22.22,36.21 21.89,36.54 21.45,36.54 U11.34 ; R138.1 7.66,57.47 7.66,55.95 8.58,55.03 11.62,55.03 v1(12.28,54.37)
VID6: length 37.3
  TOP w0.203: v1(12.66,55.13) 12.92,54.88 12.92,54.12 12.64,53.84 12.64,45.94 16.14,42.43 18.13,42.43 21.3,39.26 21.3,37.86 v1(22.06,37.1) 22.19,36.97 R247.2
  BOTTOM w0.203: U11.33 21.61,37.1 v1(22.06,37.1) 22.19,36.97 R247.2 ; v1(12.66,55.13) 12.33,55.46 8.91,55.46 8.09,56.28 8.09,58.31 R244.1
VID7: length 37.6
  TOP w0.203: v1(13.68,55.13) 13.43,54.88 13.43,53.99 13.07,53.63 13.07,46.14 16.14,43.07 18.25,43.07 21.94,39.39 21.94,38.42 v1(22.44,37.91) 22.52,37.99 R99.2
  BOTTOM w0.203: v1(13.68,55.13) 12.92,55.9 9.19,55.9 8.6,56.48 8.6,59.07 R245.1 ; U11.32 21.69,37.73 22.24,37.73 22.44,37.94 v1(22.44,37.91) 22.52,37.99 R99.2
XCLKIN: length 18.5
  TOP w0.254: U5.F23 42.79,75.36 42.79,85.13 46.22,88.56 46.22,90.08 R185.2 R184.1
N16884499: length 4.7
  TOP w0.254: Y2.2 46.83,94.79 C18.1 ; R185.1 C18.1 ; C18.1 R32.1
N16884503: length 4.7
  TOP w0.254: R38.1 R32.2 C20.1 43.4,93.61 43.05,93.96 Y2.1
N16885409: length 2.1
  TOP w0.254: v2(52.54,76.47) 52.64,76.37 U5.V23
  BOTTOM w0.254: v2(52.54,76.47) 52.92,76.85 TP10.1
N16885936: length 61.7
  TOP w0.254: v1(57.75,97.17) 57.75,89.5 56.16,87.91 56.16,85.91 54.47,84.22 49.62,84.22 49.62,84.09 46.83,81.3 46.14,81.3 45.3,80.46 45.3,77.99 46.45,76.85 46.45,75.31 U5.K23
  BOTTOM w0.203: v1(57.75,97.17) 59.83,97.17 61.64,98.97 66.72,98.97 66.97,98.72 74.92,98.72 75.25,99.05 87.19,99.05 R178.2
N16887961: length 2.8
  TOP w0.305: U5.AA23 55.04,76.76 v1(54.83,76.98)
  BOTTOM w0.381: R45.2 54.83,77.61 v1(54.83,76.98)
N16887964: length 4.3
  TOP w0.305: U5.AB23 v1(55.84,76.98)
  BOTTOM w0.381: v1(55.84,76.98) 55.84,77.61 R45.1
  BOTTOM w0.508: R45.1 55.97,78.12 ER2.1
N16971828: length 10
  TOP w0.508: Q7.4 60.92,38.62 v1(60.29,39.26) ; Q6.4 66.51,38.15 v1(65.62,38.15)
  ART02 w0.508: v1(60.29,39.26) 61.4,38.15 v1(65.62,38.15)
  BOTTOM w0.508: U8.5 59.59,39.96 v1(60.29,39.26)
N16972086: length 8.7
  TOP w0.508: v1(18.89,86.25) 18.25,86.25 U9.5
  ART02 w0.508: v1(19.61,91.74) 19.61,86.98 v1(18.89,86.25)
  BOTTOM w0.508: v1(18.89,86.25) 19.58,86.94 Q11.4 ; Q10.4 v1(19.61,91.74)
N16972137: length 12
  TOP w0.508: U9.8 13.75,86.94 v1(12.28,86.94)
  ART02 w0.508: v1(10.12,92.6) 9.74,92.22 9.74,88.03 10.83,86.94 v1(12.28,86.94)
  BOTTOM w0.508: 11.14,92.66 10.18,92.66 v1(10.12,92.6) ; 11.14,86.94 v1(12.28,86.94)
N16972188: length 4.2
  BOTTOM w0.229: 15.42,36.21 U11.5
  BOTTOM w0.254: C267.2 14.19,34.97 15.42,36.21
  BOTTOM w0.381: R68.2 C267.2
N16972208: length 1
  BOTTOM w0.381: 14.8,32.24 14.11,32.93 R68.1
N16972210: length 7.8
  BOTTOM w0.203: 15.54,35.6 U11.4
  BOTTOM w0.254: 15.54,35.6 15.2,35.27 15.2,34.94
  BOTTOM w0.381: 15.2,34.94 15.2,34.1 C267.1
  BOTTOM w0.508: C269.2 R69.2 16.23,32.24 C268.1 14.9,33.57 C267.1
N16972290: length 5.6
  BOTTOM w0.229: U11.31 21.77,38.37 22.04,38.37 22.32,38.65 22.82,38.65
  BOTTOM w0.254: 22.82,38.65 25.24,38.65 R102.1 25.62,37.23 C287.1
N16972304: length 1.2
  TOP w0.508: R66.1 22.06,98.69 22.06,97.68
N16972345: length 2.3
  BOTTOM w0.229: 14.46,35.96 U11.6
  BOTTOM w0.254: C265.1 14.19,35.96 14.46,35.96
N16972387: length 6.4
  BOTTOM w0.229: 15.31,41.96 U11.16
  BOTTOM w0.254: 15.31,41.96 13.3,43.97 13.3,44.36 R71.2
  BOTTOM w0.305: R67.1 12.55,45.67 R71.2
N16972391: length 5.1
  TOP w0.508: D4.C 14.7,78.37 14.19,78.88 U9.1 12.21,80.91 R65.2
N16972393: length 6.7
  TOP w0.508: D4.A 17.74,78.37 18,78.63 U9.4 18.51,81.42 C264.1 20.16,80.05 R64.1
N16972419: length 3.1
  BOTTOM w0.203: R71.1 15.2,43.01 15.2,42.78 15.33,42.65 15.79,42.2 U11.17
N16972439: length 16.5
  TOP w0.508: v1(61.12,28.84) 60.92,29.04 Q4.4 ; Q5.4 v1(66.64,28.72)
  ART02 w0.508: v1(61.12,28.84) 61.25,28.72 v1(66.64,28.72)
  BOTTOM w0.508: v1(61.12,28.84) 61.12,31.31 60.16,32.27 60.16,35.45 59.46,36.15 U8.8
N16972492: length 1.4
  TOP w0.508: C259.2 R65.1
N16972578: length 3.7
  BOTTOM w0.229: U11.7 14.24,36.46
  BOTTOM w0.254: R115.2 12.2,35.96 12.22,35.93 13.3,35.93 13.83,36.46 14.24,36.46
N16972692: length 9.1
  BOTTOM w0.229: 12.03,39.33 12.77,39.33 13.79,38.31 13.93,38.31 U11.10
  BOTTOM w0.254: C292.2 10.36,38.97 10.72,39.33 12.03,39.33
  BOTTOM w0.305: R105.2 7.82,39.6 8.73,38.69 9.07,38.69 C292.2
N16972744: length 8.6
  TOP w0.508: Q14.4 v1(19.23,71.26) ; Q15.4 v1(20.41,76.16)
  ART02 w0.508: v1(19.23,71.26) 19.23,74.98 v1(20.41,76.16)
  BOTTOM w0.508: 19.33,76.47 20.1,76.47 v1(20.41,76.16)
N16972799: length 13.5
  TOP w0.508: Q12.4 9.62,70.95 v1(9.62,71.39) ; Q13.4 v1(11.08,76.16)
  BOTTOM w0.508: 15.52,76.47 15.21,76.16 v1(11.08,76.16) 9.69,76.16 8.85,75.33 8.85,72.15 v1(9.62,71.39)
N16972986: length 1.2
  BOTTOM w0.508: R78.1 17.36,71.39 C281.2
N16973045: length 10.7
  TOP w0.508: R72.2 10.25,85.23 9.87,84.85 v1(9.87,84.22)
  BOTTOM w0.508: U10.1 15.52,82.88 16.36,83.73 D5.C v1(9.87,84.22)
N16973047: length 6.3
  BOTTOM w0.508: D5.A 19,84.22 19.33,83.89 U10.4 19.33,81.61 19.78,81.17 C278.1 20.95,81.14 R73.1
N16973105: length 1.4
  TOP w0.508: C277.2 10.79,82.34 R72.1
N16973186: length 1.4
  BOTTOM w0.203: D14.1 R130.2
N16973189: length 1.4
  BOTTOM w0.203: D13.1 R128.2
N16973192: length 1.4
  BOTTOM w0.203: D15.1 R132.2
N16973195: length 1.4
  BOTTOM w0.203: D16.1 R134.2
N16973214: length 1.4
  BOTTOM w0.203: D17.1 R136.2
N16973217: length 1.4
  BOTTOM w0.203: D18.1 R138.2
N16973302: length 28.9
  BOTTOM w0.508: C269.1 R69.1 18.03,30.24 ; R70.2 30.32,42.97 C271.2
  BOTTOM w0.635: 18.03,30.24 20.82,27.45 26.38,27.45 30.34,31.41 C271.2
N16973383: length 3
  BOTTOM w0.229: U11.15 14.18,42.37
  BOTTOM w0.254: R76.1 14.07,42.37 14.18,42.37
N16973403: length 4.3
  BOTTOM w0.229: U11.11 13.71,39.96 12.59,39.96
  BOTTOM w0.254: 11.3,39.96 12.59,39.96
  BOTTOM w0.381: R108.2 10.34,39.96 11.3,39.96
N16973441: length 1.3
  TOP w0.508: R61.1 C258.2
N16973681: length 3.5
  BOTTOM w0.229: 12.66,41.23 13.88,41.23 U11.13
  BOTTOM w0.254: R75.1 11.94,41.23 12.66,41.23
N16974286: length 7.3
  BOTTOM w0.229: 13.43,41.74 14.09,41.74 U11.14
  BOTTOM w0.254: 13.43,41.74 12.9,41.74 R116.2 12.66,42.27 12.66,42.88 11.62,43.93 10.43,43.93 R118.2
N16974990: length 4.1
  TOP w0.508: D3.C 54.57,36.08 53.69,35.19 v1(53.18,35.19)
  BOTTOM w0.508: R58.2 v1(53.18,35.19) 53.05,35.32 53.05,36.15
N16975003: length 6.2
  TOP w0.508: R57.1 56.27,38.99 54.58,38.99 D3.A ; D3.A 54.57,38.99 52.94,38.99 C254.1 ; D3.A 54.57,40.02 v1(54.45,40.15)
  BOTTOM w0.508: v1(54.45,40.15) 54.26,39.96 53.05,39.96
N16975056: length 7.7
  BOTTOM w0.203: U11.12 13.92,40.48
  BOTTOM w0.229: 11.01,40.99 11.43,40.57 13.82,40.57 13.92,40.48
  BOTTOM w0.254: 11.01,40.99 9.57,42.43 9.57,42.64 R107.1
  BOTTOM w0.381: R104.1 9.33,42.77 R107.1
N16975081: length 7.7
  BOTTOM w0.203: U11.2 16.6,35.23 16.6,34.82
  BOTTOM w0.381: 16.6,34.82 16.6,33.97 R126.1 19.73,30.84 19.81,30.84 20.16,30.49 20.42,30.49 R127.1
N16975136: length 19.1
  ART02 w0.254: v1(21.05,33.16) 19.75,33.16 v1(19.19,33.72) 17.19,33.72 13.09,37.82 v1(12.66,37.82)
  BOTTOM w0.203: 17.47,34.54 17.22,34.79 17.22,35.13 U11.1
  BOTTOM w0.254: 17.47,34.54 18.23,33.78 ; R126.2 v1(19.19,33.72) ; R110.1 22.06,32.15 v1(21.05,33.16)
  BOTTOM w0.305: 18.23,33.78 R126.2 ; R124.2 10.55,37.68 11.37,37.68 11.65,37.4 R125.2 12.62,37.82 v1(12.66,37.82)
N16975276: length 2.3
  BOTTOM w0.508: C251.2 R58.1
N16975672: length 4.1
  BOTTOM w0.203: U11.9 14.04,37.7 13.81,37.7
  BOTTOM w0.229: 12.54,38.68 12.73,38.68 13.17,38.24 13.71,37.7 13.81,37.7
  BOTTOM w0.254: 12.54,38.68 12.52,38.69 11.27,38.69 R124.1
N16975684: length 2.4
  BOTTOM w0.229: 14.05,36.99 U11.8
  BOTTOM w0.254: 14.05,36.99 13.23,36.99 R125.1
N17005585: length 5.2
  BOTTOM w0.203: U11.40 18.79,34.89 19.37,34.31 19.43,34.31 19.95,33.79 C279.2
  BOTTOM w0.381: C279.2 R77.1 21.48,31.58 R84.1
N17031806: length 6.7
  TOP w0.381: C344.1 76.04,105.04 v1(75.66,105.04)
  BOTTOM w0.381: R161.1 R162.2 75.53,105.17 v1(75.66,105.04) 76.04,105.04 76.44,104.65 D9.4 D9.3
N17031808: length 3.6
  TOP w0.254: R155.1 R156.2 69.76,103.27 v1(69.63,103.14)
  BOTTOM w0.254: U16.2 69.83,103.34 v1(69.63,103.14)
N17031818: length 9.8
  TOP w0.254: R156.1 69.69,104.28
  TOP w0.381: v1(67.78,105.3) 68.67,105.3 v1(69.56,104.41) 69.69,104.28
  BOTTOM w0.381: v1(67.78,105.3) 67.59,105.5 R159.2
  BOTTOM w0.508: v1(69.56,104.41) 69.76,104.61 U16.1
N17031906: length 11.4
  BOTTOM w0.381: U16.5 66.46,100.8 67.73,102.07 U16.3 72.3,102.07 73.24,103.01 C338.1 R165.1 R162.1
N17032029: length 4.4
  BOTTOM w0.254: R179.1 62.96,102.12 R169.2 63.92,103.34 U16.7
N17032033: length 5.3
  BOTTOM w0.254: R167.1 R179.2 63.46,99.96 63.85,100.35 63.85,101.74 64.17,102.07 U16.6
N17032770: length 5.9
  BOTTOM w0.254: v1(63.85,109.69) 63.65,109.49 62.32,109.49 61.94,109.11 R180.1 R170.2
  BOTTOM w0.381: U17.7 64.55,110.32 63.92,109.69 v1(63.85,109.69)
N17047933: length 9.9
  TOP w0.381: U14.2 67.02,95.52 67.4,95.9 74.01,95.9 74.51,95.39 C332.1
N17047953: length 2.2
  TOP w0.381: U14.4 71.59,94.37 C332.2
N17253373: length 4.8
  BOTTOM w0.254: R157.1 72.66,110.68 72.3,110.32 U17.2
  BOTTOM w0.305: R157.1 73.75,111.14 73.9,111.29 74.54,111.29 74.77,111.52 R158.2
N17253375: length 11.5
  BOTTOM w0.381: R158.1 73.05,111.9 72.74,111.59 U17.1 68.22,111.59 67.4,112.41 63.01,112.41 R160.2
N17253408: length 13.2
  BOTTOM w0.381: R166.1 63.55,106.7 64.63,107.78 U17.5 67.85,107.78 69.12,109.05 U17.3 72.79,109.05 73.37,108.47 C340.1 R164.1
N17253441: length 3.6
  BOTTOM w0.254: U17.6 64.23,109.05 63.9,108.73 R180.2 R168.1
N17254276: length 7.1
  TOP w0.381: v1(76.44,111) 76.42,110.98 R163.1
  BOTTOM w0.381: D10.3 D10.4 ; D10.4 75.83,109.92 75.53,109.62 R164.2 ; D10.4 v1(76.44,111) 76.96,111.52 C345.1
N17260942: length 4.7
  BOTTOM w0.254: Q22.1 66.94,95.76 66.08,96.61 64.18,96.61 R151.1
N17260992: length 7
  BOTTOM w0.254: R150.1 64,90.31 Q23.D 64.35,90.67 64.35,93.03 63.21,94.17 R151.2
N17261273: length 2.9
  BOTTOM w0.254: Q23.G 62.53,93.49 R152.1 R154.1
N17354264: length 27.8
  TOP w0.508: v1(46.07,38.02) 46.7,38.02 Q19.4 ; Q18.4 v1(40.35,38.28)
  ART02 w0.508: v1(54.07,31.38) 51.78,33.67 51.78,36.72 50.48,38.02 v1(46.07,38.02) 40.6,38.02 v1(40.35,38.28)
  BOTTOM w0.508: v1(54.07,31.38) 54.96,31.38 55.59,30.75 55.59,28.08 54.14,26.63 53.05,26.63
N17354299: length 14.6
  TOP w0.508: Q17.4 v1(46.95,28.72) ; Q16.4 v1(41.24,28.84)
  BOTTOM w0.508: v1(41.24,28.84) 41.37,28.72 v1(46.95,28.72) 50.18,28.72 51.9,30.44 53.05,30.44
N17354448: length 1.3
  TOP w0.508: C294.2 52.26,35.17 R109.1
N17354514: length 4
  TOP w0.508: D7.C 58.87,33.4 v1(59.22,33.05)
  BOTTOM w0.508: 58.49,32.32 v1(59.22,33.05) ; 58.49,32.32 58.49,30.59 U12.1 ; 58.49,32.32 R100.2
N17354516: length 11.1
  TOP w0.508: R101.1 C291.1 57.82,31.45 D7.A 58.44,30.84 59.49,30.84 v1(59.91,31.26)
  BOTTOM w0.508: v1(59.91,31.26) 60.29,30.88 60.29,27.07 59.85,26.63 U12.4
N17354559: length 2.3
  BOTTOM w0.508: C286.2 R100.1
N17460832: length 8.1
  TOP w0.231: R23.2 60.09,15.43 59.65,15 59.65,14.43 D2.3 60.14,12.93 60.14,10.68 60.04,10.13 60.04,10.05 J3.2
N17460836: length 9.2
  TOP w0.231: R24.2 60.24,14.8 60.24,14.29 60.61,13.92 D2.2 60.72,12.96 60.72,10.45 J3.3
N17465473: length 4.8
  BOTTOM w0.254: R178.1 TP8.1
N17472139: length 2.2
  BOTTOM w0.254: U13.13 71.97,84.85 R205.1
N17472149: length 5.7
  BOTTOM w0.254: U13.14 72.47,84.09 72.72,84.34 72.72,85.39 72.25,85.87 72.23,85.87 R205.2 72.1,87.01 R204.1 C364.1
N17472208: length 6.1
  BOTTOM w0.254: U13.10 70.47,83.43 70.2,83.71 69.43,83.71 68.29,84.85 68.29,85.21 68.15,85.35 68.15,85.37 67.53,85.99 R209.1 R207.1
N17472210: length 1.1
  BOTTOM w0.254: R207.2 65.24,87.14
N17472223: length 7.1
  BOTTOM w0.254: C367.2 66.26,86.12 R209.2 R212.2 C369.2 C374.2 64.23,84.85 63.9,84.52 63.9,82.9 C371.2
N17472242: length 27.8
  BOTTOM w0.254: U13.12 71.47,83.8 70.96,84.31 C368.2
  BOTTOM w0.305: R206.2 61.31,74.37 62.68,75.74 62.68,77.52 61.97,78.23 61.97,86.52 64.26,88.81 68.38,88.81 70.35,86.85 70.35,86.35 70.83,85.87 C366.1 C368.2
N17472254: length 2.5
  BOTTOM w0.254: U13.8 69.08,82.16 67.53,83.71 R211.1
N17472271: length 1
  BOTTOM w0.203: C369.1 65.55,83.71
  BOTTOM w0.254: 65.55,83.71 R211.2
N17472288: length 3.5
  BOTTOM w0.254: R212.1 67.48,84.85 69.1,83.23 69.81,83.23 69.97,83.07 U13.9
N17472302: length 6.1
  BOTTOM w0.203: U13.7 68.69,81.66 67.86,82.49 R218.2 66.36,82.49 R215.1 66.31,82.45 65.84,81.98 65.55,81.98 65.29,81.73 C373.2
  BOTTOM w0.254: C371.1 64.33,81.45 C373.2
N17472317: length 3.1
  BOTTOM w0.203: C373.1 67.48,81.45 R218.1 68.24,81.47 68.56,81.16 U13.6
N17472378: length 25.7
  BOTTOM w0.254: U13.11 70.97,83.44 70.95,83.46 70.95,83.63 69.94,84.65 C368.1
  BOTTOM w0.305: C368.1 69.94,85.61 C370.2 69.81,86.63 68.16,88.28 64.48,88.28 62.5,86.3 62.5,78.45 63.21,77.74 63.21,75.52 62.32,74.63 R210.2
N17472408: length 5
  BOTTOM w0.203: U13.5 68.43,80.66 68.24,80.85 66.22,80.85 R214.2
  BOTTOM w0.254: R213.2 R214.2
N17472451: length 2
  TOP w0.254: v1(67.99,80.25) 68.04,80.3 C372.2
  BOTTOM w0.254: U13.4 68.08,80.16 v1(67.99,80.25)
N17472474: length 4.6
  BOTTOM w0.203: R216.2 R217.2 66.13,79.26 66.54,79.67 69.26,79.67 U13.3
N17472541: length 5.6
  BOTTOM w0.254: C391.2 76.52,80.91 75.26,80.91 75.02,81.16 U13.19
  BOTTOM w0.508: C391.2 76.9,81.3 C358.2 R188.1
N17472572: length 2.8
  BOTTOM w0.254: U13.22 76.81,79.66 R192.1
N17472629: length 3
  TOP w0.381: v1(75.28,79.03) 75.81,78.5 R189.1
  BOTTOM w0.254: U13.23 75.15,79.16 v1(75.28,79.03)
N17472645: length 2.3
  TOP w0.381: v1(75.15,80.28) 74.51,79.64 R200.1
  BOTTOM w0.254: U13.21 75.03,80.16 v1(75.15,80.28)
N17472992: length 3.9
  BOTTOM w0.254: 76.67,84.85 76.67,84.8 C360.1 75.54,83.67 75.54,83.49 75.15,83.1 75.15,82.82 74.49,82.16 U13.17
N17485645: length 4.4
  BOTTOM w0.203: U13.2 68.79,79.16 68.14,78.5 66,78.5
  BOTTOM w0.254: 66,78.5 R219.2
N17488147: length 1.4
  BOTTOM w0.254: R192.2 78.45,78.76 C361.1
N17489529: length 1.6
  BOTTOM w0.254: R215.2 65.29,82.77 64.48,83.58 C374.1
N17492409: length 5.3
  TOP w0.381: R200.2 74.39,78.12 75.66,76.85 R203.2 v1(76.42,75.58)
  BOTTOM w0.381: v1(76.42,75.58) 76.47,75.63 Q21.4
N17495070: length 9.2
  TOP w0.381: R189.2 82.77,78.5 v1(83.78,77.49) 83.78,76.72
  BOTTOM w0.381: Q20.4 85.26,75.63 83.78,77.1 v1(83.78,77.49)
N17497213: length 1.4
  BOTTOM w0.381: R201.1 77.43,70.37 C363.2
N17500314: length 3.4
  BOTTOM w0.254: R30.2 60.16,92.47 59.15,91.46 R233.1 57.74,91.33 U18.2
N17502184: length 1.8
  BOTTOM w0.254: R181.1 58.04,90.06 U18.3
N17503406: length 5.2
  BOTTOM w0.254: Q3.1 55.21,93.49 59.02,93.49 C353.2 R30.1
N17507007: length 6.4
  BOTTOM w0.305: R182.1 57.88,95.14 Q3.3 57.11,94.88 57.11,96.03 55.84,97.3 Q24.1
N17511574: length 3.8
  TOP w0.254: R184.2 49.37,91.71 50.39,92.73 X1.3
N17523163: length 2.9
  BOTTOM w0.203: C355.2 53.3,94.38 53.18,94.5 52.8,94.5 52.29,95.01 Q25.1
N17523415: length 5.4
  BOTTOM w0.203: 53.18,91.2 Q26.1 51.4,91.2 49.37,93.23 Q25.3
N17532743: length 10.5
  BOTTOM w0.254: R11.1 80.36,46.12 80.36,47.89 80.74,48.28 R177.1 81.12,52.09 82.06,53.03 U6.16
N17532745: length 9.5
  BOTTOM w0.254: U6.17 82.43,52.38 81.63,51.58 81.63,49.04 R176.1 82.64,48.28 83.02,47.89 83.02,45.99 R10.1
N17532747: length 8.8
  BOTTOM w0.254: R9.1 83.66,45.48 84.29,46.12 84.29,47.77 83.78,48.28 R14.1 82.13,49.8 82.13,51.32 82.54,51.73 U6.18
N17532758: length 6.8
  BOTTOM w0.254: U6.20 84.42,50.43 84.93,49.92 R13.1 85.18,48.28 85.56,47.89 85.56,45.99 R8.1
N17535586: length 2.6
  BOTTOM w0.254: R33.2 74.26,53.58 74.36,53.68 U6.6
N17535589: length 2.7
  BOTTOM w0.254: U6.7 74.39,54.33 74.12,54.6 R35.2
N17535592: length 2.8
  BOTTOM w0.254: U6.8 74.67,54.98 74.03,55.62 R41.2
N17535595: length 3
  BOTTOM w0.254: U6.9 74.78,55.63 73.78,56.63 R37.2
N17535696: length 3.1
  BOTTOM w0.254: U6.15 84.81,53.68 85.11,53.38 85.11,52.87 R34.1
N17535699: length 2.5
  BOTTOM w0.254: U6.14 84.91,54.33 R40.1
N17535702: length 2.2
  BOTTOM w0.254: U6.13 85.06,54.98 85.28,54.75 R36.1
N17535705: length 2.3
  BOTTOM w0.254: U6.12 85.04,55.63 85.44,56.02 R42.1
N17535726: length 6.9
  BOTTOM w0.254: R34.2 87.21,52.21 89.12,50.31 89.12,49.68 J4.1
N17535729: length 6
  BOTTOM w0.254: J4.2 87.86,53.48 R40.2
N17535732: length 5.5
  BOTTOM w0.254: J4.3 89.13,54.75 R36.2
N17535735: length 5
  BOTTOM w0.254: R42.2 90.4,56.02 J4.4
N17540184: length 2.7
  TOP w0.254: R220.1 C375.2 Q27.1
N17540190: length 7.2
  TOP w0.254: Q28.3 74.71,12.08 D1.A2
  BOTTOM w0.254: R222.1 75.21,12.59 D1.A2
N17540204: length 5.7
  TOP w0.254: R221.1 69.31,12.33 Q27.3 69.81,11.83 70.96,11.83 72.35,10.43 Q28.1
N17540688: length 2.9
  TOP w0.254: D1.C2 79.52,16.27 R223.2
N17540854: length 3
  TOP w0.254: D1.A1 72.67,13.58 R224.1
N17542536: length 1.7
  TOP w0.254: C378.2 70.58,17.92 70.01,17.36 U19.16
N17542621: length 20.5
  TOP w0.254: J2.1 80.48,19.95 R225.1 C379.2 78.7,17.29 77.18,15.76 76.16,15.76 74.89,17.03 74.26,17.03 71.39,14.16 67.61,14.16 67.15,14.62 U19.9
N17543309: length 3.6
  TOP w0.254: R226.1 R227.1 C381.2 66.64,15.15 U19.8
N17544610: length 7.4
  TOP w0.254: v1(65.12,19.16) U19.24
  BOTTOM w0.254: v1(65.12,19.16) 65.27,19.01 65.27,15.48 65.5,15.26 D20.2
N17544613: length 1.5
  BOTTOM w0.254: R228.2 D20.1
N17544663: length 10
  TOP w0.254: U19.23 66.65,19.69 66.26,20.08 v1(65.12,20.08)
  BOTTOM w0.254: D21.2 66.89,14.87 65.75,16.02 65.75,19.45 v1(65.12,20.08)
N17544665: length 1.6
  BOTTOM w0.254: R229.2 66.64,11.17 D21.1
N17544725: length 6.2
  TOP w0.254: v1(70.58,17.03) 70.4,16.86 U19.15
  BOTTOM w0.254: v1(70.58,17.03) 68.29,14.75 D22.2
N17544727: length 1.5
  BOTTOM w0.254: R230.2 D22.1
N17544738: length 7.1
  TOP w0.254: v1(71.47,17.03) 70.79,16.36 U19.14
  BOTTOM w0.254: v1(71.47,17.03) 70.2,15.76 70.2,13.5 D23.2
N17544740: length 1.6
  BOTTOM w0.254: R231.2 69.43,11.17 D23.1
N17552651:
  vias: v1(18.89,23.64) v1(18.89,21.99) v1(18.89,20.59) v1(20.16,23.64) v1(20.16,21.99) v1(20.16,20.59) v1(21.43,20.59) v1(22.7,23.64) v1(22.7,21.99) v1(22.7,20.59)
N17568086: length 6.1
  BOTTOM w0.254: 70.83,57.8 72.18,57.8 72.43,58.05 73.24,58.05 75.02,56.28 U6.10
N17581232: length 2.5
  BOTTOM w0.254: R240.1 80.36,97.04 80.99,96.41 U20.7
N17581329: length 2.4
  BOTTOM w0.254: U20.8 80.86,97.68 80.48,98.06 C390.2
N17581616: length 3.2
  TOP w0.254: v1(88.99,97.68) 88.1,96.79 C388.1
  BOTTOM w0.254: U20.1 v1(88.99,97.68)
N17581619: length 1.1
  TOP w0.254: C388.2 88.99,95.39 v1(89.12,95.27)
N17581966: length 2.4
  BOTTOM w0.254: C389.1 80.23,94.88 80.48,95.14 U20.6
N17581969: length 1
  BOTTOM w0.254: R241.1 C389.2
N17582251: length 3.4
  BOTTOM w0.254: R242.2 R243.1 U20.5
N17600922: length 1.4
  BOTTOM w0.203: D24.1 R244.2
N17601217: length 1.4
  BOTTOM w0.203: D25.1 R245.2

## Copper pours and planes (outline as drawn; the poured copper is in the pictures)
GND_SIGNAL on ART02 (solid shape): outline of 2304 points within 32.71,98.34 79.42,112.82
GND_SIGNAL on ART03 (solid shape): outline of 2306 points within 32.71,98.34 79.42,112.82
P12V_FLT on TOP (solid shape): outline of 1323 points within 1.74,19.32 90.26,99.33
P12V_FLT on BOTTOM (solid shape): 91.02,97.3 91.79,97.3 92.95,96.13 92.95,84.01 91.9,82.96 91.91,82.95 91.91,78.37 92.29,77.99 93.44,77.99 93.56,77.87 93.56,72.53 92.42,71.39 87.47,71.39 87.09,71.77 87.09,75.96 87.34,76.22 87.34,82.69 87.7,83.05 87.7,83.07 91.48,86.86 91.48,94.81 90.26,96.03 86.83,96.03 86.71,96.15 86.71,96.54 86.83,96.66 88.36,96.66 88.93,97.23 88.94,97.24 88.97,97.25 89.08,97.25 89.19,97.29 89.2,97.3 89.5,97.3
P12V_FLT on BOTTOM (solid shape): 9.74,99.2 9.74,92.83 9.69,92.78 9.69,92.42 9.74,92.37 9.74,85.36 8.85,84.47 8.85,77.87 7.97,76.98 7.97,64.79 7.2,64.02 4.03,64.02 3.77,64.28 3.77,74.44 3.14,75.07 1.87,75.07 1.62,75.33 1.62,81.04 4.66,81.04 4.66,82.18 3.14,82.18 3.14,81.04 1.62,81.04 1.62,86.88 5.04,86.88 5.04,87.52 4.66,87.52 4.66,86.88 1.62,86.88 1.62,88.03 2.63,89.04 5.04,89.04 5.04,89.93 4.54,89.93 4.54,89.04 2.63,89.04 2.76,89.17 2.76,92.73 5.17,92.73 5.17,93.61 4.54,93.61 4.54,92.73 2.76,92.73 2.76,94.88 5.17,94.88 5.17,95.9 4.54,95.9 4.54,94.88 2.76,94.88 2.76,99.33 2.89,99.46 9.49,99.46
P12V_FLT on BOTTOM (solid shape): outline of 92 points within 26,19.19 70.96,28.21
